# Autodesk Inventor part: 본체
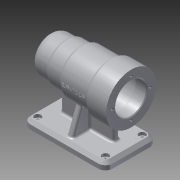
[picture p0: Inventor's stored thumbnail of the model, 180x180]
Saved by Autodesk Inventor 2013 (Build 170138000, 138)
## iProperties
Created: 2016-06
Part Number: 본체
Material: 알루미늄 6061
Document SubType Name: Modeling
Designer: Administrator
Density: 2.71 g/cm^3
Mass: 673.897 g
Surface Area: 647.23 cm^2
Volume: 248.671 cm^3
Author: Administrator
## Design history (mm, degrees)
sketch "스케치1"
  geometry: L1 (0, 0)-(25, 0); L2 (25, 0)-(25, 25); L3 (25, 25)-(0, 25); L4 (0, 25)-(0, 0); L5 (25, 0)-(45, 0); L6 (45, 0)-(45, 27); L7 (45, 27)-(25, 27); L8 (25, 27)-(25, 0); L9 (45, 0)-(84, 0); L10 (84, 0)-(84, 30); L11 (84, 30)-(45, 30); L12 (45, 30)-(45, 0); L13 (84, 0)-(112, 0); L14 (112, 0)-(112, 34); L15 (112, 34)-(84, 34); L16 (84, 34)-(84, 0)
  constraints: 32 end point, 8 parallel, 4 horizontal, 4 perpendicular
  dimensions: "d0" = 25 distance of L2.end L3.end; "d2" = 45 distance between parallel lines of L6 L4; "d3" = 84 distance between parallel lines of L10 L4; "d4" = 112 distance between parallel lines of L14 L4; "d5" = 25 distance of L3.end L1.start; "d6" = 27 distance of L7.end L1.end; "d7" = 30 distance of L11.end L5.end; "d8" = 34 distance of L13.end L14.end
revolve "회전1" sketch "스케치1" stored, may be unused: angle "d9" = 90 deg
sketch "스케치2"
  geometry: L1 (0, -25)-(0, 25) reference; L2 (0, 25)-(25, 25) reference; L3 (25, 25)-(25, 27) reference; L4 (25, 27)-(45, 27) reference; L5 (45, 27)-(45, 30) reference; L6 (45, 30)-(84, 30) reference; L7 (84, 30)-(84, 34) reference; L8 (84, 34)-(112, 34) reference; L9 (112, 34)-(112, -34) reference; L10 (112, -34)-(84, -34) reference; L11 (84, -34)-(84, -30) reference; L12 (84, -30)-(45, -30) reference; L13 (45, -30)-(45, -27) reference; L14 (45, -27)-(25, -27) reference; L15 (25, -27)-(25, -25) reference; L16 (25, -25)-(0, -25) reference; L17 (112, -34)-(112, 34) reference; L18 (112, 0)-(97, 0); L19 (97, 0)-(97, 21); L20 (97, 21)-(112, 21); L21 (112, 21)-(112, 0); L22 (97, 0)-(43, 0); L23 (43, 0)-(43, 21); L24 (46, 24)-(94, 24); L25 (97, 21)-(97, 0); L26 (43, 0)-(31, 0); L27 (31, 0)-(31, 20.7); L28 (31.3, 21)-(43, 21); L29 (43, 21)-(43, 0); L30 (31, 0)-(13, 0); L31 (13, 0)-(13, 17.2); L32 (13.3, 17.5)-(31, 17.5); L33 (31, 17.5)-(31, 0); L34 (13, 0)-(9, 0); L35 (9, 0)-(9, 15.7); L36 (9.3, 16)-(13, 16); L37 (13, 16)-(13, 0); L38 (9, 0)-(6, 0); L39 (6, 0)-(6, 7.5); L40 (9, 10.5)-(9, 10.5); L41 (9, 10.5)-(9, 0); A1 r 0.3 centre (9.3, 15.7) between (9.3, 16) and (9, 15.7); A2 r 0.3 centre (13.3, 17.2) between (13.3, 17.5) and (13, 17.2); A3 r 0.3 centre (31.3, 20.7) between (31.3, 21) and (31, 20.7); A4 r 3 centre (9, 7.5) between (9, 10.5) and (6, 7.5); A5 r 3 centre (46, 21) between (46, 24) and (43, 21); A6 r 3 centre (94, 21) between (97, 21) and (94, 24); 7 further points
  constraints: 48 end point, 12 parallel, 12 point on circle, 12 point on line, 12 tangent, 6 centre point, 6 horizontal, 6 perpendicular, 3 equal radius, 1 midpoint
  dimensions: "d10" = 15 distance of L19.end L20.end; "d13" = 12 distance of point (31, 21) L28.end; "d14" = 18 distance of point (13, 17.5) L32.end; "d15" = 4 distance of point (9, 16) L36.end; "d16" = 3 distance of point (6, 10.5) L40.end; "d17" = 54 distance of point (43, 24) point (97, 24); "d18" = 21 distance between parallel lines of L18 L20; "d19" = 24 distance between parallel lines of L22 L24; "d20" = 21 distance between parallel lines of L26 L28; "d21" = 17.5 distance between parallel lines of L30 L32; "d22" = 16 distance between parallel lines of L34 L36; "d23" = 10.5 distance between parallel lines of L38 L40; "d24" = 0.3 radius of A1; "d25" = 3 radius of A4; "d27" = 3 radius of A5
revolve "회전2" sketch "스케치2" stored, may be unused: angle "d26" = 90 deg
node "작업 평면1"
sketch "스케치3"
  geometry: L1 (-112, 34)-(-112, -34) reference; L2 (-10, -35)-(-102, -35); L3 (-112, -25)-(-112, 25); L4 (-102, 35)-(-10, 35); L5 (0, 25)-(0, -25); A1 r 10 centre (-10, -25) between (-10, -35) and (0, -25); A2 r 10 centre (-10, 25) between (0, 25) and (-10, 35); A3 r 10 centre (-102, 25) between (-102, 35) and (-112, 25); A4 r 10 centre (-102, -25) between (-112, -25) and (-102, -35); 5 further points
  constraints: 9 point on line, 8 end point, 8 point on circle, 8 tangent, 4 centre point, 3 equal radius, 2 parallel, 1 horizontal, 1 perpendicular
  dimensions: "d29" = 112 distance of point (0, -35) point (-112, -35); "d31" = 70 distance of point (0, 35) point (0, -35); "d32" = 35 distance from line of point (0, 0) L4; "d33" = 10 radius of A1
extrude "돌출1" join sketch "스케치3" distance "d34" = 10; taper "d35" = 0 deg
sketch "스케치4"
  geometry: L1 (0, 25)-(0, -25) reference; L2 (10, -35)-(102, -35) reference; L3 (112, -25)-(112, 25) reference; L4 (52, 28)-(60, 28); L5 (60, 28)-(60, -28); L6 (60, -28)-(52, -28); L7 (52, -28)-(52, 28); L8 (52, 28)-(60, -28); L9 (60, 28)-(52, -28); L10 (20, 4)-(92, 4); L11 (92, 4)-(92, -4); L12 (92, -4)-(20, -4); L13 (20, -4)-(20, 4); L14 (20, 4)-(92, -4); L15 (92, 4)-(20, -4); 5 further points
  constraints: 24 end point, 7 midpoint, 4 parallel, 2 horizontal, 2 perpendicular, 1 horizontal alignment
  dimensions: "d36" = 56 distance from line of L3 point (56, 0); "d37" = 8 distance of L10.end L11.end; "d38" = 8 distance of L5.end L6.end; "d39" = 7 distance between parallel lines of L2 L6; "d40" = 20 distance between parallel lines of L13 L1
extrude "돌출2" join sketch "스케치4" stored distance "d41" = 10; taper "d42" = 0 deg
feature "면 기울기1" dims angle "d43" = 20 deg
sketch "스케치5"
  geometry: A1 r 10 centre (10, -25) between (0, -25) and (10, -35) reference; A2 r 10 centre (102, -25) between (102, -35) and (112, -25) reference; A3 r 10 centre (102, 25) between (112, 25) and (102, 35) reference; A4 r 10 centre (10, 25) between (10, 35) and (0, 25) reference; 5 further points
  constraints: 4 coincident
hole "구멍1" sketch "스케치5" at (10, 25), (10, -25), (102, -25), (102, 25) diameter "d44" = 5; stored, may be unused: countersink angle "d48" = 90 deg, drill point angle "d50" = 118 deg; dims "d45" = 6, "d46" = 9, "d47" = 4, "d49" = 8
sketch "스케치6"
  geometry: C1 r 21 at (0, 0) reference; 4 further points
  constraints: 1 vertical alignment, 5 other
  dimensions: "d51" = 26 distance of C1.centre point (0, 26); "d54" = 360 deg dimension on C1.centre point (0, 26) (derived)
hole "구멍2" sketch "스케치6" at (0, 26), (-26, 0), (0, -26), (26, 0) diameter "d56" = 3.242; stored, may be unused: countersink angle "d60" = 90 deg, drill point angle "d62" = 118 deg; dims "d57" = 8, "d58" = 9, "d59" = 4, "d61" = 11
fillet "모깎기1" dims "d63" = 10
fillet "모깎기2" dims "d64" = 3
fillet "모깎기3" dims "d65" = 3
fillet "모깎기4" dims "d66" = 3
fillet "모깎기5" dims "d67" = 3
chamfer "모따기1" distance "d68" = 4; stored, may be unused: second distance "d69" = 2, angle "d70" = 45 deg
chamfer "모따기2" distance "d74" = 1; stored, may be unused: second distance "d75" = 2, angle "d76" = 45 deg
node "작업 평면2"
sketch "스케치7"
  geometry: L1 (47.5, -34)-(47.5, 34) reference; 2 further points
  constraints: 1 horizontal alignment, 1 other
  dimensions: "d71" = 48 distance from line of L1 point (-0.5, 0)
feature "엠보싱1" sketch "스케치7" dims "d72" = 0.5, "d73" = 0
node "솔리드1"
node "절단 모서리 투영1"
